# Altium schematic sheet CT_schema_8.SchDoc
size 308 x 210 mm
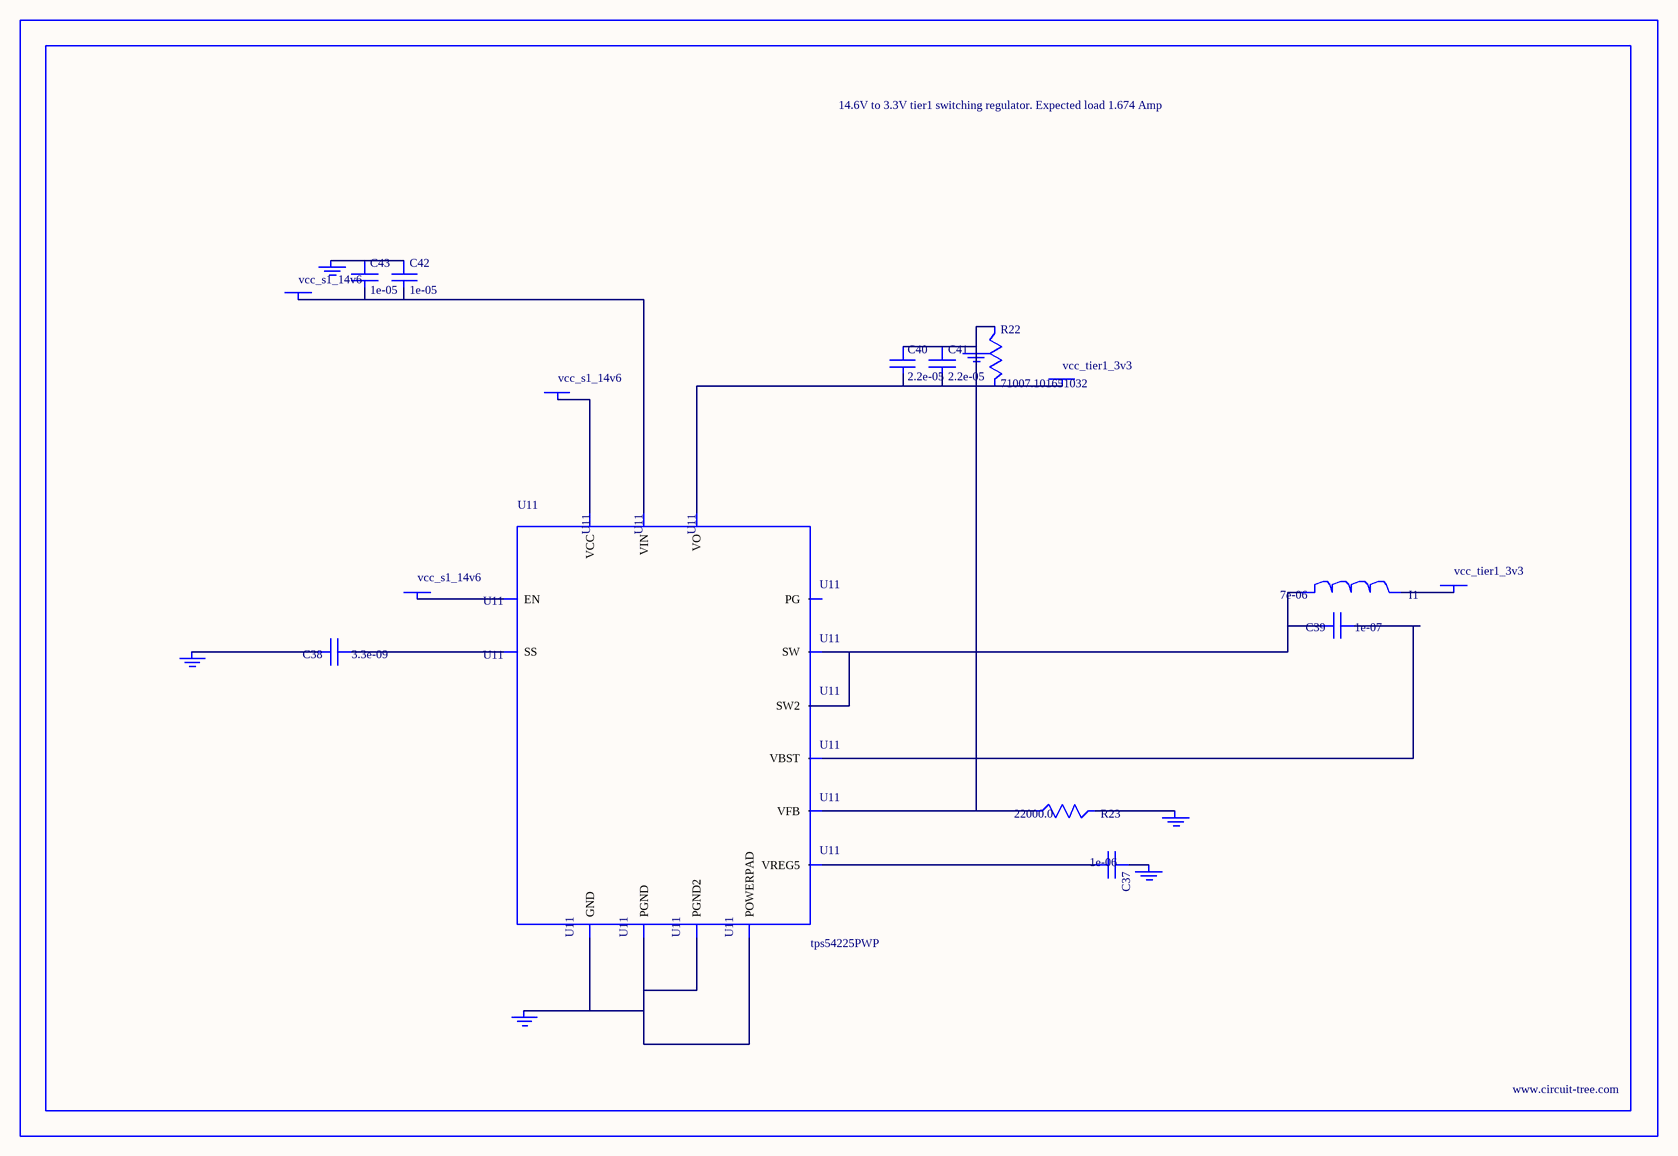
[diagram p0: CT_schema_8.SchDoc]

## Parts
BORDER7  (no value)
C37  1e-06  [C0603]
C38  3.3e-09  [C0402]
C39  1e-07  [C0402]
C40  2.2e-05  [C1210]
C41  2.2e-05  [C1210]
C42  1e-05  [C1206]
C43  1e-05  [C1206]
GND_INSTANCE_7_0  (no value)
GND_INSTANCE_7_1  (no value)
GND_INSTANCE_7_2  (no value)
GND_INSTANCE_7_3  (no value)
GND_INSTANCE_7_4  (no value)
GND_INSTANCE_7_5  (no value)
I1  7e-06  [DR1040]
POWER_INSTANCE_7_0  vcc_tier1_3v3
POWER_INSTANCE_7_1  vcc_s1_14v6
POWER_INSTANCE_7_2  vcc_tier1_3v3
POWER_INSTANCE_7_3  vcc_s1_14v6
POWER_INSTANCE_7_4  vcc_s1_14v6
R22  71007.101651032  [R0603]
R23  22000.0  [R0603]
U11  tps54225PWP  [HTSSOP14]

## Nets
NetC37_1: C37.1 GND_INSTANCE_7_2.0(GND)
NetC37_2: C37.2 U11.3(VREG5)
NetC38_1: C38.1 U11.4(SS)
NetC38_2: C38.2 GND_INSTANCE_7_3.0(GND)
NetC39_1: C39.1 U11.12(VBST)
NetC39_2: C39.2 I1.1 U11.10(SW) U11.11(SW2)
NetC40_1: C40.1 C41.1 GND_INSTANCE_7_0.0(GND) R22.1 R23.1 U11.2(VFB)
NetC40_2: C40.2 C41.2 POWER_INSTANCE_7_0.0(PWR) R22.2 U11.1(VO)
NetC42_1: C42.1 C43.1 GND_INSTANCE_7_5.0(GND)
NetC42_2: C42.2 C43.2 POWER_INSTANCE_7_3.0(PWR) U11.13(VIN)
NetGND_INSTANCE_7_1_0: GND_INSTANCE_7_1.0(GND) R23.2
NetGND_INSTANCE_7_4_0: GND_INSTANCE_7_4.0(GND) U11.5(GND) U11.8(PGND) U11.9(PGND2) U11.15(POWERPAD)
NetI1_2: I1.2 POWER_INSTANCE_7_2.0(PWR)
NetPOWER_INSTANCE_7_1_0: POWER_INSTANCE_7_1.0(PWR) U11.7(EN)
NetPOWER_INSTANCE_7_4_0: POWER_INSTANCE_7_4.0(PWR) U11.14(VCC)

Not connected (* = marked no-connect by the designer): U11 6(PG)

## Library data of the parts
BORDER7 = BORDER_PAGE7
C37 = C0603C105K3RACTU
C38 = C0402C332K3RAC
C39 = C0402C104K3RACTU
C40 C41 = GRM32ER61E226ME15L
C42 C43 = C1206C106K3RACTU
GND_INSTANCE_7_0-GND_INSTANCE_7_5 = GND
I1 = DR1040-7R0-R
POWER_INSTANCE_7_0-POWER_INSTANCE_7_4 = PWR
R22 = R22
R23 = RC0603JR-0722KL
